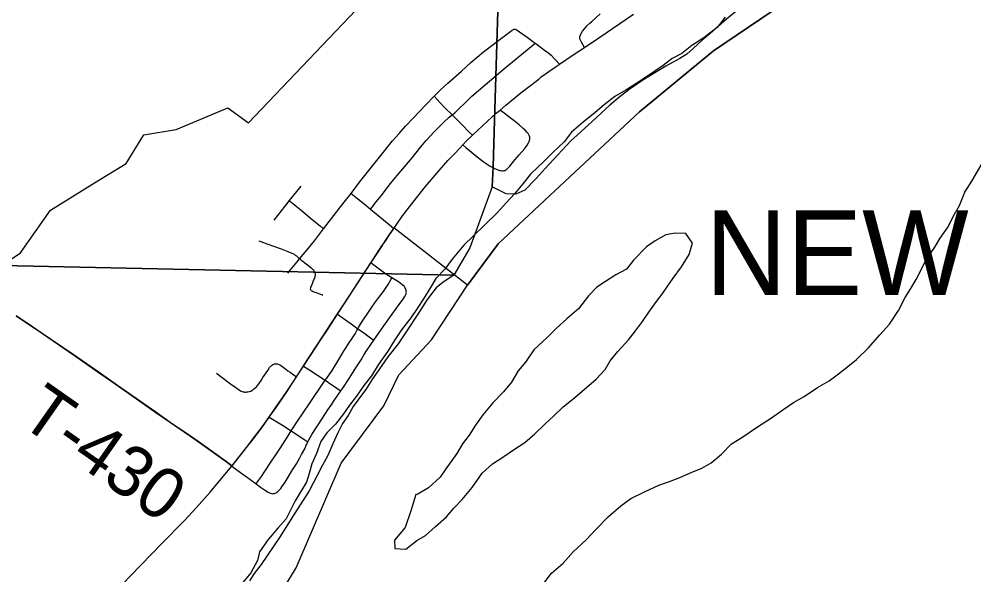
# Model space of a CAD drawing. Extents: x 6.3 to 40.3, y 9 to 31.
# Drawn here: x 10.708 to 11.78, y 24.889 to 25.513 of the extents above; entities that cross this region are included whole.
import ezdxf

# ---------------------------------------------------------------- set-up
doc = ezdxf.new("R2010")
doc.units = 0
for name, color, linetype in [('Default', 7, 'Continuous'), ('GM_X_City_Street', 7, 'Continuous'), ('GM_X_Corporation', 7, 'Continuous'), ('GM_X_Corporation_Text', 7, 'Continuous'), ('GM_X_Major_River', 7, 'Continuous'), ('GM_X_Section', 7, 'Continuous'), ('GM_X_State_Route', 7, 'Continuous'), ('GM_X_Township_Road', 7, 'Continuous'), ('GM_X_Township_Road_Text', 7, 'Continuous'), ('SH_Cut_Line', 7, 'Continuous')]:
    doc.layers.add(name, color=color, linetype=linetype)

msp = doc.modelspace()

# ---------------------------------------------------------------- linework, layer by layer
at = {"layer": 'Default'}
msp.add_lwpolyline([(10.9858, 24.8421), (11.0192, 24.8969), (11.0698, 25.0142), (11.1175, 25.0787), (11.1344, 25.1135), (11.171, 25.1528), (11.2115, 25.2141), (11.2461, 25.2602), (11.3094, 25.32), (11.4046, 25.4084), (11.4875, 25.4768), (11.5799, 25.5397), (11.6392, 25.5915), (11.7003, 25.6676), (11.7623, 25.7099), (11.814, 25.7608)], dxfattribs=at)
at = {"layer": 'GM_X_City_Street'}
msp.add_line((11.0117, 25.3088), (11.0248, 25.3251), dxfattribs=at)
for points in [[(11.3428, 25.4806), (11.3395, 25.4866), (11.3382, 25.489), (11.3379, 25.4897), (11.3377, 25.4904), (11.3377, 25.4911), (11.3376, 25.4919), (11.3377, 25.4928), (11.3379, 25.4938), (11.3383, 25.4947), (11.3388, 25.4957), (11.3408, 25.4989), (11.3431, 25.502), (11.3456, 25.5048), (11.3488, 25.5079), (11.3511, 25.51), (11.3603, 25.5184)], [(11.0809, 25.317), (11.0903, 25.3294), (11.1037, 25.3465), (11.1113, 25.3559), (11.1274, 25.3758), (11.1347, 25.3842), (11.142, 25.3923), (11.1575, 25.4088), (11.1648, 25.4163), (11.1741, 25.4259), (11.1817, 25.4334), (11.1896, 25.4408), (11.2047, 25.4542), (11.2153, 25.4638), (11.2297, 25.4757), (11.2526, 25.4933), (11.2602, 25.4991), (11.2612, 25.4998), (11.2617, 25.5002), (11.2623, 25.5005), (11.263, 25.5008)], [(11.263, 25.5008), (11.264, 25.5011), (11.2651, 25.5011), (11.2661, 25.5007), (11.2784, 25.4921), (11.2876, 25.4856), (11.2882, 25.4852), (11.2996, 25.4767), (11.3023, 25.4745), (11.3053, 25.4719), (11.3089, 25.4684), (11.3102, 25.467), (11.3148, 25.462)], [(11.1028, 25.2992), (11.1061, 25.3035), (11.1076, 25.3055), (11.1145, 25.3143), (11.1252, 25.328), (11.1327, 25.3372), (11.1496, 25.357), (11.1592, 25.3692), (11.1653, 25.3763), (11.1742, 25.3859), (11.1851, 25.3969), (11.191, 25.4024), (11.1929, 25.404), (11.1944, 25.4051), (11.1956, 25.406), (11.1973, 25.4075), (11.2005, 25.4104), (11.2103, 25.42), (11.2166, 25.4259), (11.2539, 25.458), (11.2847, 25.4832), (11.2876, 25.4856)], [(11.2171, 25.3822), (11.2131, 25.3862), (11.2055, 25.394), (11.1972, 25.4022), (11.1944, 25.4051), (11.1859, 25.4135), (11.181, 25.4186), (11.1741, 25.4259)], [(11.2062, 25.3713), (11.2098, 25.3684), (11.2138, 25.3651), (11.2244, 25.3566), (11.2304, 25.352), (11.2324, 25.3506), (11.2349, 25.3489), (11.2364, 25.3479), (11.2391, 25.3463), (11.2419, 25.345), (11.2449, 25.3438), (11.2469, 25.3431), (11.248, 25.3428), (11.2493, 25.3426), (11.2509, 25.3424), (11.2518, 25.3424), (11.2527, 25.3426), (11.2536, 25.3428), (11.2544, 25.3433), (11.2553, 25.3439), (11.2565, 25.3449), (11.2575, 25.3459), (11.2589, 25.3475), (11.2632, 25.3529), (11.2697, 25.3604), (11.2758, 25.3674), (11.2784, 25.3709), (11.2801, 25.3735), (11.2805, 25.3743), (11.2809, 25.3751), (11.2813, 25.3763), (11.2815, 25.3782), (11.2815, 25.3793), (11.2814, 25.3802), (11.2813, 25.381), (11.2809, 25.382), (11.2805, 25.3827), (11.2797, 25.384), (11.2787, 25.3853), (11.2761, 25.388), (11.2742, 25.3896), (11.2696, 25.3937), (11.2638, 25.3984), (11.258, 25.403), (11.2526, 25.4071), (11.2481, 25.4105)], [(11.05, 25.2773), (11.0589, 25.2887), (11.0679, 25.3003), (11.0732, 25.3071), (11.0809, 25.317)], [(11.0809, 25.317), (11.0975, 25.3036), (11.1028, 25.2992), (11.1132, 25.2905), (11.1235, 25.2822), (11.129, 25.2777)], [(10.9946, 25.2869), (11.007, 25.3028), (11.0117, 25.3088)], [(11.0117, 25.3088), (11.0122, 25.3083), (11.0148, 25.3062), (11.0188, 25.3029), (11.027, 25.2962), (11.0371, 25.2878), (11.0463, 25.2804), (11.05, 25.2773)], [(11.0231, 25.2437), (11.0311, 25.2532), (11.0397, 25.2639), (11.0488, 25.2757), (11.05, 25.2773)], [(10.9775, 25.2637), (10.9795, 25.263), (10.9873, 25.2601), (11.0025, 25.2547), (11.01, 25.2519), (11.0127, 25.2508), (11.0156, 25.2494), (11.0169, 25.2486), (11.0182, 25.2478), (11.0195, 25.2468), (11.0207, 25.2458), (11.0219, 25.2448), (11.0231, 25.2437)], [(11.0098, 25.2274), (11.0129, 25.2312), (11.0204, 25.2403), (11.0231, 25.2437)], [(11.0493, 25.2025), (11.0481, 25.203), (11.0417, 25.2053), (11.0383, 25.2066), (11.0371, 25.2071), (11.0363, 25.2077), (11.0358, 25.2084), (11.0355, 25.2095), (11.0357, 25.2108), (11.0359, 25.2116), (11.0364, 25.213), (11.0385, 25.2182), (11.0404, 25.2234), (11.0407, 25.2243), (11.0408, 25.2252), (11.0409, 25.2259), (11.0408, 25.2267), (11.0407, 25.2274), (11.0405, 25.2283), (11.04, 25.2292), (11.0396, 25.2299), (11.039, 25.2307), (11.0384, 25.2313), (11.037, 25.2325), (11.0306, 25.2374), (11.0272, 25.24), (11.0257, 25.2413), (11.0237, 25.2431), (11.0231, 25.2437)], [(10.9298, 25.1153), (10.9361, 25.1103), (10.9457, 25.1033), (10.9515, 25.0991), (10.9547, 25.0969), (10.9563, 25.0958), (10.9574, 25.0952), (10.9588, 25.0946), (10.9598, 25.0943), (10.9608, 25.0941), (10.9618, 25.094), (10.9628, 25.094), (10.9639, 25.0941), (10.9649, 25.0942), (10.967, 25.0947), (10.9682, 25.0951), (10.9694, 25.0957), (10.9705, 25.0965), (10.9719, 25.0975), (10.973, 25.0984), (10.9746, 25.0998), (10.9759, 25.1014), (10.9772, 25.1033), (10.9799, 25.1071), (10.982, 25.1102), (10.9857, 25.1155), (10.9874, 25.1183), (10.9895, 25.1214), (10.9909, 25.1232), (10.9917, 25.1239), (10.9926, 25.1247), (10.9933, 25.1251), (10.9941, 25.1254), (10.995, 25.1257), (10.996, 25.1258), (10.9971, 25.1257), (10.998, 25.1256), (10.9991, 25.1254), (11.0001, 25.1249), (11.0016, 25.1241), (11.0033, 25.1229), (11.006, 25.1209), (11.01, 25.118), (11.0125, 25.1162), (11.0154, 25.1141), (11.0197, 25.1111)]]:
    msp.add_lwpolyline(points, dxfattribs=at)
at = {"layer": 'GM_X_Corporation'}
for points in [[(10.6262, 25.1947), (10.7099, 25.2503), (10.7436, 25.2981), (10.793, 25.3287), (10.8284, 25.3506), (10.8482, 25.3828), (10.8847, 25.3887), (10.9426, 25.4128), (10.9657, 25.3962), (11.169, 25.6097)], [(11.5799, 25.5397), (11.4875, 25.4768), (11.4046, 25.4084), (11.3094, 25.32), (11.2461, 25.2602), (11.2115, 25.2141), (11.1288, 25.2782), (11.1279, 25.2769), (11.1223, 25.2687), (11.1199, 25.2651), (11.1188, 25.2636), (11.1175, 25.2616), (11.1168, 25.2605), (11.1151, 25.258), (11.1055, 25.2434), (11.103, 25.2395), (11.0835, 25.2096), (11.0654, 25.1819), (11.0533, 25.1633), (11.0486, 25.156), (11.0273, 25.1236), (11.0195, 25.1116), (11.0077, 25.0937), (10.9965, 25.0774), (10.9888, 25.0665), (10.9811, 25.0555), (10.9711, 25.0422), (10.962, 25.0303), (10.947, 25.0113), (10.9394, 25.0168), (10.9158, 25.034), (10.9005, 25.0447), (10.8779, 25.0599), (10.8616, 25.0713), (10.8398, 25.0867), (10.8261, 25.0963), (10.8123, 25.1059), (10.7981, 25.1159), (10.769, 25.136), (10.7331, 25.1605), (10.7172, 25.1714), (10.7049, 25.1796)]]:
    msp.add_lwpolyline(points, dxfattribs=at)
at = {"layer": 'GM_X_Major_River'}
for points in [[(11.5009, 25.5147), (11.4916, 25.5031), (11.4767, 25.4915), (11.4632, 25.4829), (11.4523, 25.474), (11.4414, 25.4684), (11.4313, 25.4603), (11.4137, 25.4486), (11.4017, 25.4408), (11.3894, 25.4326), (11.377, 25.4255), (11.365, 25.4162), (11.3549, 25.4077), (11.3415, 25.3968), (11.3284, 25.3856), (11.3202, 25.3748), (11.3072, 25.3628), (11.2971, 25.3528), (11.2822, 25.3385), (11.2737, 25.3277), (11.2644, 25.3165), (11.2551, 25.3065), (11.2447, 25.2953), (11.2305, 25.2814), (11.2178, 25.269), (11.2074, 25.259), (11.1944, 25.2432), (11.1863, 25.2321), (11.1762, 25.2216), (11.1699, 25.2113), (11.1622, 25.1986), (11.1559, 25.189), (11.1478, 25.1775), (11.1374, 25.164), (11.1293, 25.1514), (11.1223, 25.1399), (11.1112, 25.1245), (11.1038, 25.1122), (11.0953, 25.1015), (11.0871, 25.0896), (11.079, 25.0795), (11.0723, 25.0696), (11.0634, 25.058), (11.0538, 25.0484), (11.0471, 25.0384), (11.042, 25.025), (11.0369, 25.0135), (11.0337, 25.0025), (11.0308, 24.993), (11.0238, 24.9814), (11.0183, 24.9719), (11.0132, 24.9623), (11.0081, 24.9516), (10.9988, 24.9412), (10.988, 24.9285), (10.978, 24.9146), (10.9759, 24.9051), (10.9682, 24.8913), (10.9589, 24.8798)], [(11.2964, 24.8783), (11.306, 24.8907), (11.3191, 24.9019), (11.3302, 24.9146), (11.3452, 24.9285), (11.3556, 24.9397), (11.3697, 24.9544), (11.3836, 24.9664), (11.3948, 24.9746), (11.4102, 24.9821), (11.4264, 24.9896), (11.4384, 24.9936), (11.4497, 24.9983), (11.4625, 25.0039), (11.4746, 25.0086), (11.4851, 25.0145), (11.4967, 25.0242), (11.5078, 25.0358), (11.5195, 25.0432), (11.5382, 25.0557), (11.5517, 25.0643), (11.5656, 25.074), (11.5775, 25.0822), (11.5896, 25.0889), (11.6045, 25.099), (11.6173, 25.1068), (11.6278, 25.1146), (11.6383, 25.1227), (11.648, 25.1305), (11.6618, 25.1436), (11.6744, 25.1583), (11.6852, 25.1702), (11.6952, 25.1856), (11.7029, 25.2001), (11.7091, 25.2101), (11.715, 25.2205), (11.7202, 25.2304), (11.726, 25.2419), (11.736, 25.2565), (11.7419, 25.2668), (11.7511, 25.2795), (11.7566, 25.291), (11.7636, 25.3033), (11.7698, 25.3185), (11.7775, 25.3308), (11.7893, 25.3504)], [(11.1536, 24.9789), (11.1478, 24.9606), (11.1417, 24.9419), (11.1298, 24.928), (11.13, 24.9185), (11.1425, 24.9176), (11.1548, 24.9273), (11.1646, 24.9332), (11.1758, 24.9433), (11.1881, 24.9541), (11.1963, 24.9637), (11.2056, 24.9734), (11.2167, 24.9869), (11.2282, 25.003), (11.2398, 25.0135), (11.2525, 25.0217), (11.263, 25.0291), (11.2758, 25.0373), (11.287, 25.0473), (11.2985, 25.0581), (11.3086, 25.0674), (11.319, 25.0775), (11.3299, 25.086), (11.3426, 25.0969), (11.356, 25.1085), (11.3661, 25.1193), (11.3716, 25.1289), (11.3801, 25.1397), (11.3924, 25.1528), (11.4002, 25.1628), (11.408, 25.1732), (11.415, 25.1835), (11.422, 25.1931), (11.4317, 25.2062), (11.4424, 25.2219), (11.4516, 25.2346), (11.4605, 25.2484), (11.4641, 25.261), (11.4567, 25.2719), (11.4445, 25.2724), (11.4343, 25.2703), (11.4223, 25.2637), (11.4126, 25.2571), (11.3977, 25.242)], [(11.3977, 25.242), (11.3899, 25.232), (11.3782, 25.2257), (11.3666, 25.2179), (11.3569, 25.2117), (11.3472, 25.202), (11.3361, 25.1874), (11.323, 25.1762), (11.3114, 25.1657), (11.301, 25.1553), (11.2861, 25.1414), (11.2768, 25.1275), (11.2683, 25.1179), (11.2609, 25.1052), (11.252, 25.0941), (11.2401, 25.0821), (11.2289, 25.0686), (11.2204, 25.0567), (11.2134, 25.0456), (11.206, 25.036), (11.1994, 25.0249), (11.1872, 25.0079), (11.1809, 24.9984), (11.1678, 24.9867), (11.1558, 24.9793), (11.1536, 24.9789)]]:
    msp.add_lwpolyline(points, dxfattribs=at)
at = {"layer": 'GM_X_Section'}
msp.add_lwpolyline([(10.2824, 26.2364), (11.2666, 26.2073), (11.242, 25.3993), (11.2405, 25.3466), (11.2394, 25.3243), (11.2143, 25.2557), (11.1962, 25.2251), (10.2864, 25.2447)], close=True, dxfattribs=at)
for points in [[(11.5166, 25.5242), (11.5024, 25.5123), (11.4841, 25.4964), (11.4751, 25.4887), (11.4647, 25.4794), (11.4576, 25.4733), (11.4497, 25.4682), (11.4418, 25.4639), (11.4343, 25.4596), (11.4084, 25.4441), (11.3941, 25.4344), (11.3829, 25.4255), (11.3713, 25.4158), (11.3616, 25.4069), (11.3515, 25.3977), (11.3347, 25.3823), (11.3276, 25.3761), (11.3131, 25.3603), (11.2989, 25.3449), (11.2885, 25.3338), (11.2758, 25.3207), (11.2657, 25.316), (11.255, 25.3166), (11.2394, 25.3243), (11.2405, 25.3466), (11.242, 25.3993), (11.2666, 26.2073)], [(10.2864, 25.2447), (11.1962, 25.2251), (11.1842, 25.2173), (11.1764, 25.2111), (11.1663, 25.198), (11.1549, 25.1804), (11.1442, 25.164), (11.1338, 25.1483), (11.1223, 25.1337), (11.1093, 25.1153), (11.1049, 25.1088), (11.0975, 25.0969), (11.0938, 25.0919), (11.0834, 25.0777), (11.0775, 25.0678), (11.0712, 25.0586), (11.066, 25.0483), (11.0605, 25.0361), (11.0547, 25.0227), (11.0488, 25.012), (11.0429, 25.0005), (11.0337, 24.9833), (11.0178, 24.9581), (11.0004, 24.9309), (10.9801, 24.9006), (10.9723, 24.8903), (10.9667, 24.8822)]]:
    msp.add_lwpolyline(points, dxfattribs=at)
at = {"layer": 'GM_X_State_Route'}
for points in [[(11.2452, 25.4081), (11.2481, 25.4105), (11.2546, 25.4161), (11.2714, 25.4299), (11.2779, 25.4348), (11.2915, 25.4453), (11.2944, 25.4476), (11.3029, 25.4538), (11.3112, 25.4595), (11.3143, 25.4616), (11.3148, 25.462), (11.3303, 25.4725), (11.3428, 25.4806), (11.3588, 25.4914), (11.398, 25.5179)], [(11.1387, 25.2918), (11.1542, 25.3121), (11.1644, 25.3246), (11.1797, 25.3427), (11.1896, 25.3538), (11.1965, 25.3611), (11.2028, 25.3678), (11.2062, 25.3713), (11.2106, 25.3759), (11.2165, 25.3816), (11.2171, 25.3822), (11.234, 25.3981), (11.2437, 25.4068), (11.2452, 25.4081)], [(11.0782, 25.2007), (11.0837, 25.2091), (11.1032, 25.239), (11.1057, 25.2429), (11.1153, 25.2574), (11.117, 25.26), (11.1177, 25.261), (11.119, 25.2631), (11.1201, 25.2646), (11.1225, 25.2682), (11.1281, 25.2764), (11.129, 25.2777), (11.1329, 25.2836), (11.1387, 25.2918)], [(10.9472, 25.0107), (10.9622, 25.0298), (10.9713, 25.0416), (10.9813, 25.055), (10.989, 25.066), (10.9967, 25.0768), (11.0079, 25.0932), (11.0197, 25.1111), (11.0275, 25.123), (11.0488, 25.1555), (11.0535, 25.1628), (11.0656, 25.1814), (11.0782, 25.2007)], [(10.5848, 24.6304), (10.604, 24.6503), (10.6208, 24.6678), (10.6271, 24.6744), (10.6527, 24.7008), (10.6799, 24.729), (10.7007, 24.7504), (10.7038, 24.7535), (10.7543, 24.8058), (10.8131, 24.8664), (10.8327, 24.8872), (10.8454, 24.9), (10.8683, 24.9237), (10.8938, 24.95), (10.9069, 24.9641), (10.9227, 24.9816), (10.9375, 24.9992), (10.9472, 25.0107)]]:
    msp.add_lwpolyline(points, dxfattribs=at)
at = {"layer": 'GM_X_Township_Road'}
for points in [[(11.1267, 25.2223), (11.1184, 25.2276), (11.1124, 25.2318), (11.108, 25.2352), (11.1032, 25.239)], [(11.0885, 25.1651), (11.0893, 25.1664), (11.0926, 25.172), (11.0954, 25.1765), (11.0989, 25.1816), (11.1042, 25.1892), (11.1096, 25.1968), (11.1171, 25.2067), (11.1202, 25.2113), (11.1226, 25.2149), (11.1244, 25.2181), (11.1267, 25.2223)], [(11.1426, 25.2085), (11.1423, 25.2095), (11.142, 25.2102), (11.1414, 25.2112), (11.1409, 25.212), (11.1403, 25.2127), (11.138, 25.2147), (11.1341, 25.2177), (11.1267, 25.2223)], [(11.1064, 25.1521), (11.1123, 25.1607), (11.1175, 25.1684), (11.125, 25.1789), (11.1337, 25.1909), (11.139, 25.1978), (11.1414, 25.2014), (11.1425, 25.2035), (11.1427, 25.2041), (11.1429, 25.2055), (11.143, 25.2063), (11.1429, 25.2073), (11.1426, 25.2085)], [(10.7108, 25.1752), (10.7051, 25.1791)], [(10.9472, 25.0107), (10.9396, 25.0163), (10.916, 25.0335), (10.9007, 25.0441), (10.8781, 25.0594), (10.8618, 25.0708), (10.84, 25.0862), (10.8263, 25.0958), (10.8125, 25.1054), (10.7983, 25.1154), (10.7692, 25.1355), (10.7333, 25.16), (10.7174, 25.1708), (10.7108, 25.1752)], [(11.0656, 25.1814), (11.0709, 25.1776), (11.081, 25.1704), (11.0885, 25.1651)], [(11.0517, 25.1072), (11.0536, 25.1097), (11.0596, 25.1184), (11.0672, 25.1305), (11.0725, 25.1395), (11.0755, 25.1441), (11.0784, 25.1488), (11.0817, 25.1539), (11.0853, 25.1594), (11.0869, 25.1623), (11.0885, 25.1651)], [(11.0885, 25.1651), (11.0937, 25.1615), (11.1013, 25.1561), (11.1037, 25.1542), (11.1064, 25.1521)], [(11.0694, 25.0953), (11.0716, 25.0984), (11.0781, 25.1082), (11.0871, 25.1222), (11.0921, 25.1302), (11.0955, 25.1361), (11.0982, 25.1402), (11.1064, 25.1521)], [(11.0275, 25.123), (11.0334, 25.1192), (11.0432, 25.1128), (11.0517, 25.1072)], [(11.0137, 25.0505), (11.0159, 25.054), (11.0193, 25.0592), (11.0278, 25.0718), (11.0334, 25.08), (11.0517, 25.1072)], [(11.0517, 25.1072), (11.0556, 25.1046), (11.0648, 25.0985), (11.0664, 25.0974), (11.0694, 25.0953)], [(11.0325, 25.0382), (11.0331, 25.0395), (11.0348, 25.0429), (11.0369, 25.0465), (11.0488, 25.0646), (11.0549, 25.0739), (11.0586, 25.0795), (11.0628, 25.0856), (11.0694, 25.0953)], [(10.989, 25.066), (10.9964, 25.0614), (11.0038, 25.0569), (11.0137, 25.0505)], [(10.9744, 24.991), (10.977, 24.9948), (10.9802, 24.9994), (10.9836, 25.0046), (10.9916, 25.0164), (10.9957, 25.0226), (11.0016, 25.0314), (11.0043, 25.0356), (11.0103, 25.045), (11.0137, 25.0505)], [(11.0137, 25.0505), (11.0146, 25.0499), (11.028, 25.0411), (11.0325, 25.0382)], [(10.9967, 24.981), (10.9977, 24.9816), (10.9986, 24.9823), (10.9996, 24.9833), (11.0007, 24.9845), (11.0019, 24.9859), (11.0031, 24.9876), (11.0069, 24.993), (11.0153, 25.0068), (11.0196, 25.0136), (11.0232, 25.0201), (11.0254, 25.0239), (11.0289, 25.0305), (11.0302, 25.0333), (11.0325, 25.0382)], [(10.9472, 25.0107), (10.9568, 25.0039), (10.9672, 24.9961), (10.9744, 24.991)], [(10.9744, 24.991), (10.9794, 24.9874), (10.9839, 24.9843), (10.9879, 24.9818), (10.9893, 24.9811), (10.9906, 24.9805), (10.9919, 24.9802), (10.993, 24.98), (10.9939, 24.9801), (10.9949, 24.9802), (10.9958, 24.9806), (10.9967, 24.981)]]:
    msp.add_lwpolyline(points, dxfattribs=at)
at = {"layer": 'SH_Cut_Line'}
msp.add_lwpolyline([(10.9858, 24.8421), (11.0192, 24.8969), (11.0698, 25.0142), (11.1175, 25.0787), (11.1344, 25.1135), (11.171, 25.1528), (11.2115, 25.2141), (11.2461, 25.2602), (11.3094, 25.32), (11.4046, 25.4084), (11.4875, 25.4768), (11.5799, 25.5397), (11.6392, 25.5915), (11.7003, 25.6676), (11.7623, 25.7099), (11.814, 25.7608)], dxfattribs=at)

# ---------------------------------------------------------------- texts
at = {"layer": 'GM_X_Corporation_Text'}
msp.add_text('NEW MATAMORAS', height=0.094697, rotation=0, dxfattribs=at).set_placement((11.4786, 25.2031))
at = {"layer": 'GM_X_Township_Road_Text'}
msp.add_text('T-430', height=0.05682, rotation=324.9447, dxfattribs=at).set_placement((10.7064, 25.0597))

doc.saveas('drawing.dxf')
